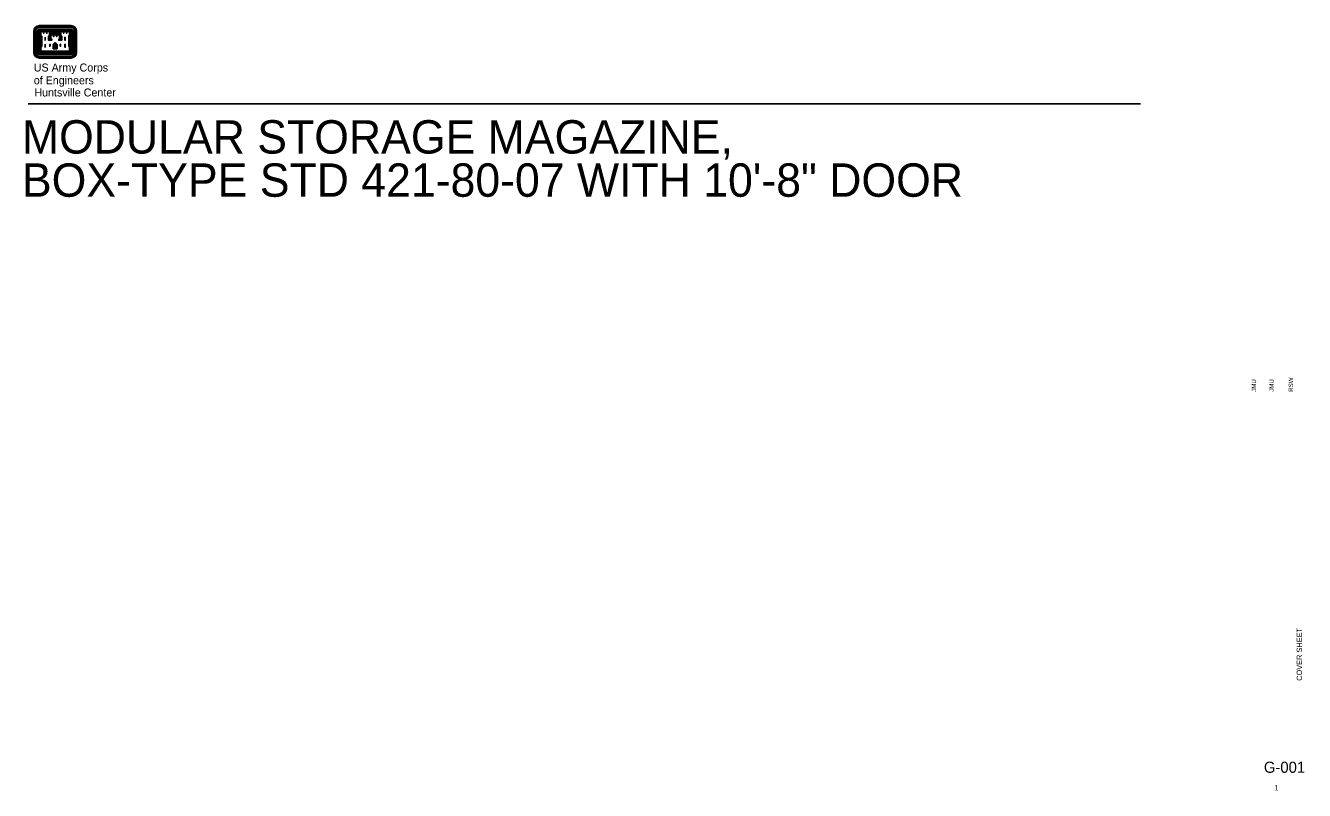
# Model space of a CAD drawing. Extents: x 0.3 to 2.69, y 0.14 to 1.57.
import ezdxf

# ---------------------------------------------------------------- set-up
doc = ezdxf.new("R2010")
doc.units = 0
doc.layers.add('G-ANNO-TEXT', color=7, linetype='Continuous')
doc.layers.add('G-ANNO-TTLB', color=7, linetype='Continuous')

msp = doc.modelspace()

# ---------------------------------------------------------------- linework, layer by layer
at = {"layer": 'G-ANNO-TEXT'}
msp.add_line((0.3008, 1.4245), (2.3865, 1.4245), dxfattribs=at)
at = {"layer": 'G-ANNO-TTLB'}
for p, q in [((0.3116, 1.5605), (0.3116, 1.5206)), ((0.3123, 1.5605), (0.3123, 1.5206)), ((0.3132, 1.5605), (0.3132, 1.5206)), ((0.314, 1.5605), (0.314, 1.5206)), ((0.3148, 1.5605), (0.3148, 1.5206)), ((0.3182, 1.5605), (0.3182, 1.5206)), ((0.3191, 1.5605), (0.3191, 1.5206)), ((0.3199, 1.5605), (0.3199, 1.5206)), ((0.3208, 1.5605), (0.3208, 1.5206)), ((0.3216, 1.5605), (0.3216, 1.5206)), ((0.3813, 1.5711), (0.3222, 1.5711)), ((0.3813, 1.5704), (0.3222, 1.5704)), ((0.3813, 1.5696), (0.3222, 1.5696)), ((0.3813, 1.5688), (0.3222, 1.5688)), ((0.3813, 1.5679), (0.3222, 1.5679)), ((0.3813, 1.5646), (0.3222, 1.5646)), ((0.3813, 1.5637), (0.3222, 1.5637)), ((0.3813, 1.5628), (0.3222, 1.5628)), ((0.3813, 1.562), (0.3222, 1.562)), ((0.3813, 1.5612), (0.3222, 1.5612)), ((0.3224, 1.5605), (0.3224, 1.5209)), ((0.3233, 1.5605), (0.3233, 1.5218)), ((0.3425, 1.5603), (0.3608, 1.5603)), ((0.3425, 1.5595), (0.3608, 1.5595)), ((0.3425, 1.5588), (0.3608, 1.5588)), ((0.3802, 1.5605), (0.3802, 1.5218)), ((0.381, 1.5605), (0.381, 1.5209)), ((0.3818, 1.5605), (0.3818, 1.5206)), ((0.3827, 1.5605), (0.3827, 1.5206)), ((0.3836, 1.5605), (0.3836, 1.5206)), ((0.3844, 1.5605), (0.3844, 1.5206)), ((0.3852, 1.5605), (0.3852, 1.5206)), ((0.3886, 1.5605), (0.3886, 1.5206)), ((0.3895, 1.5605), (0.3895, 1.5206)), ((0.3903, 1.5605), (0.3903, 1.5206)), ((0.3911, 1.5605), (0.3911, 1.5206)), ((0.3917, 1.5605), (0.3917, 1.5206)), ((0.324, 1.5521), (0.324, 1.5316)), ((0.3248, 1.5512), (0.3248, 1.5326)), ((0.3425, 1.5578), (0.3608, 1.5578)), ((0.3425, 1.557), (0.3608, 1.557)), ((0.3425, 1.5562), (0.3608, 1.5562)), ((0.3425, 1.5553), (0.3608, 1.5553)), ((0.3787, 1.5512), (0.3787, 1.5326)), ((0.3794, 1.552), (0.3794, 1.5318)), ((0.3813, 1.52), (0.3222, 1.52)), ((0.3813, 1.5192), (0.3222, 1.5192)), ((0.3813, 1.5183), (0.3222, 1.5183)), ((0.3813, 1.5175), (0.3222, 1.5175)), ((0.3813, 1.5167), (0.3222, 1.5167)), ((0.3813, 1.5132), (0.3222, 1.5132)), ((0.3813, 1.5124), (0.3222, 1.5124)), ((0.3813, 1.5116), (0.3222, 1.5116)), ((0.3813, 1.5108), (0.3222, 1.5108)), ((0.381, 1.5209), (0.3224, 1.5209)), ((0.3802, 1.5218), (0.3233, 1.5218)), ((0.3477, 1.5275), (0.3477, 1.534)), ((0.3477, 1.5275), (0.3557, 1.5275)), ((0.3486, 1.5275), (0.3486, 1.534)), ((0.3494, 1.5275), (0.3494, 1.534)), ((0.3503, 1.5275), (0.3503, 1.534)), ((0.3512, 1.5275), (0.3512, 1.534)), ((0.3523, 1.5275), (0.3523, 1.534)), ((0.3531, 1.5275), (0.3531, 1.534)), ((0.354, 1.5275), (0.354, 1.534)), ((0.3548, 1.5275), (0.3548, 1.534)), ((0.3557, 1.5275), (0.3557, 1.534)), ((0.3813, 1.5101), (0.3222, 1.5101))]:
    msp.add_line(p, q, dxfattribs=at)
for points in [[(0.324, 1.5605), (0.324, 1.5529), (0.3257, 1.5512), (0.3257, 1.5326), (0.324, 1.5308), (0.324, 1.5223), (0.3795, 1.5223), (0.3795, 1.5308), (0.3777, 1.5326), (0.3777, 1.5512), (0.3795, 1.5529), (0.3795, 1.5605), (0.3722, 1.5605), (0.3665, 1.5605), (0.3613, 1.5605), (0.3613, 1.5529), (0.3631, 1.5512), (0.3631, 1.5445), (0.3591, 1.5445), (0.3591, 1.5451), (0.3608, 1.5468), (0.3608, 1.5544), (0.3534, 1.5544), (0.3478, 1.5544), (0.3425, 1.5544), (0.3425, 1.5468), (0.3443, 1.5451), (0.3443, 1.5445), (0.3403, 1.5445), (0.3403, 1.5512), (0.3421, 1.5529), (0.3421, 1.5605), (0.3346, 1.5605), (0.329, 1.5605), (0.324, 1.5605)], [(0.3248, 1.5597), (0.3248, 1.5533), (0.3265, 1.5515), (0.3265, 1.5322), (0.3248, 1.5305), (0.3248, 1.5233), (0.3787, 1.5233), (0.3787, 1.5305), (0.377, 1.5322), (0.377, 1.5515), (0.3787, 1.5533), (0.3787, 1.5597), (0.3735, 1.5597), (0.3735, 1.5567), (0.373, 1.5567), (0.373, 1.5597), (0.3679, 1.5597), (0.3679, 1.5567), (0.3674, 1.5567), (0.3674, 1.5597), (0.3622, 1.5597), (0.3622, 1.5533), (0.3639, 1.5515), (0.3639, 1.5436), (0.3583, 1.5436), (0.3583, 1.5455), (0.36, 1.5471), (0.36, 1.5537), (0.3548, 1.5537), (0.3548, 1.5506), (0.3543, 1.5506), (0.3543, 1.5537), (0.3491, 1.5537), (0.3491, 1.5506), (0.3486, 1.5506), (0.3486, 1.5537), (0.3435, 1.5537), (0.3435, 1.5471), (0.3452, 1.5455), (0.3452, 1.5436), (0.3394, 1.5436), (0.3394, 1.5515), (0.3412, 1.5533), (0.3412, 1.5597), (0.3361, 1.5597), (0.3361, 1.5567), (0.3356, 1.5567), (0.3356, 1.5597), (0.3303, 1.5597), (0.3303, 1.5567), (0.3299, 1.5567), (0.3299, 1.5597), (0.3248, 1.5597)], [(0.3327, 1.5493), (0.3327, 1.5436), (0.3332, 1.5436), (0.3332, 1.5493), (0.3327, 1.5493)], [(0.3327, 1.5362), (0.3327, 1.5306), (0.3332, 1.5306), (0.3332, 1.5362), (0.3327, 1.5362)], [(0.3417, 1.5513), (0.3411, 1.5508), (0.3411, 1.5452), (0.343, 1.5452), (0.3417, 1.5465), (0.3417, 1.5514)], [(0.3416, 1.5362), (0.3416, 1.5324), (0.3422, 1.5324), (0.3422, 1.5362), (0.3416, 1.5362)], [(0.3617, 1.5513), (0.3622, 1.5508), (0.3622, 1.5452), (0.3605, 1.5452), (0.3617, 1.5465), (0.3617, 1.5514)], [(0.3617, 1.5362), (0.3617, 1.5324), (0.3612, 1.5324), (0.3612, 1.5362), (0.3617, 1.5362)], [(0.3707, 1.5493), (0.3707, 1.5436), (0.3701, 1.5436), (0.3701, 1.5493), (0.3707, 1.5493)], [(0.3707, 1.5362), (0.3707, 1.5306), (0.3701, 1.5306), (0.3701, 1.5362), (0.3707, 1.5362)]]:
    msp.add_lwpolyline(points, dxfattribs=at)
for centre, major_axis, start_param, end_param in [((0.3221, 1.5606), (-0.0104, 0), 4.712389, 6.283185), ((0.3221, 1.5606), (-0.00984, 0), 4.712389, 6.283185), ((0.3221, 1.5606), (-0.00899, 0), 4.712389, 6.283185), ((0.3221, 1.5606), (-0.00815, 0), 4.712389, 6.283185), ((0.3221, 1.5606), (-0.0073, 0), 4.712389, 6.283185), ((0.3221, 1.5606), (-0.00392, 0), 4.712389, 6.283185), ((0.3221, 1.5606), (-0.00307, 0), 4.712389, 6.283185), ((0.3221, 1.5606), (-0.00222, 0), 4.712389, 6.283185), ((0.3221, 1.5606), (0.00138, 0), 1.570796, 3.141593), ((0.3221, 1.5606), (-0.000532, 0), 4.712389, 6.283185), ((0.3813, 1.5606), (-0.0104, 0), 3.141593, 4.712389), ((0.3813, 1.5606), (0.00984, 0), 0, 1.570796), ((0.3813, 1.5606), (0.00899, 0), 0, 1.570796), ((0.3813, 1.5606), (0.00815, 0), 0, 1.570796), ((0.3813, 1.5606), (0.0073, 0), 0, 1.570796), ((0.3813, 1.5606), (-0.00392, 0), 3.141593, 4.712389), ((0.3813, 1.5606), (-0.00307, 0), 3.141593, 4.712389), ((0.3813, 1.5606), (-0.00222, 0), 3.141593, 4.712389), ((0.3813, 1.5606), (-0.00138, 0), 3.141593, 4.712389), ((0.3813, 1.5606), (-0.000532, 0), 3.141593, 4.712389), ((0.3532, 1.5336), (0.00541, 0), 1.844255, 3.072783), ((0.3532, 1.5336), (-0.00457, 0), 4.947481, 6.214375), ((0.3532, 1.5336), (-0.00372, 0), 4.947481, 6.214375), ((0.3532, 1.5336), (-0.00288, 0), 4.947481, 6.214375), ((0.3502, 1.5336), (0.00203, 0), 0.06881, 1.335704), ((0.3502, 1.5336), (0.00288, 0), 0.06881, 1.335704), ((0.3502, 1.5336), (-0.00372, 0), 3.210403, 4.477297), ((0.3532, 1.5336), (-0.00203, 0), 4.947481, 6.214375), ((0.3502, 1.5336), (0.00457, 0), 0.06881, 1.335704), ((0.3502, 1.5336), (0.00541, 0), 0.06881, 1.298435), ((0.3221, 1.5206), (0.0104, 0), 3.141593, 4.712389), ((0.3221, 1.5206), (0.00984, 0), 3.141593, 4.712389), ((0.3221, 1.5206), (-0.00899, 0), 0, 1.570796), ((0.3221, 1.5206), (0.00815, 0), 3.141593, 4.712389), ((0.3221, 1.5206), (0.0073, 0), 3.141593, 4.712389), ((0.3221, 1.5206), (0.00392, 0), 3.141593, 4.712389), ((0.3221, 1.5206), (0.00307, 0), 3.141593, 4.712389), ((0.3221, 1.5206), (0.00222, 0), 3.141593, 4.712389), ((0.3221, 1.5206), (0.00138, 0), 3.141593, 4.712389), ((0.3221, 1.5206), (0.000532, 0), 3.141593, 4.712389), ((0.3813, 1.5206), (0.0104, 0), 4.712389, 6.283185), ((0.3813, 1.5206), (0.00392, 0), 4.712389, 6.283185), ((0.3813, 1.5206), (0.00307, 0), 4.712389, 6.283185), ((0.3813, 1.5206), (0.00222, 0), 4.712389, 6.283185), ((0.3813, 1.5206), (0.00138, 0), 4.712389, 6.283185), ((0.3813, 1.5206), (0.000532, 0), 4.712389, 6.283185), ((0.3813, 1.5206), (0.0073, 0), 4.712389, 6.283185), ((0.3813, 1.5206), (0.00815, 0), 4.712389, 6.283185), ((0.3813, 1.5206), (0.00899, 0), 4.712389, 6.283185), ((0.3813, 1.5206), (0.00984, 0), 4.712389, 6.283185)]:
    msp.add_ellipse(centre, major_axis=major_axis, ratio=0.999936, start_param=start_param, end_param=end_param, dxfattribs=at)

# ---------------------------------------------------------------- texts
for s, height, p in [('US Army Corps', 0.015, (0.3116, 1.485)), ('of Engineers', 0.015, (0.3116, 1.4611)), ('Huntsville Center', 0.015, (0.3127, 1.4383)), ('MODULAR STORAGE MAGAZINE, ', 0.0625, (0.2894, 1.3313)), ('BOX-TYPE STD 421-80-07 WITH 10\'-8" DOOR', 0.0625, (0.2894, 1.2504)), ('G-001', 0.02083, (2.6175, 0.1712)), ('1', 0.01, (2.6369, 0.1382))]:
    msp.add_text(s, height=height, dxfattribs=at).set_placement(p)
for s, height, p in [('JMU', 0.00833, (2.603, 0.885)), ('JMU', 0.00833, (2.6359, 0.885)), ('RSW', 0.00833, (2.6722, 0.885)), ('COVER SHEET', 0.01, (2.689, 0.3435))]:
    msp.add_text(s, height=height, rotation=90, dxfattribs=at).set_placement(p)

doc.saveas('drawing.dxf')
